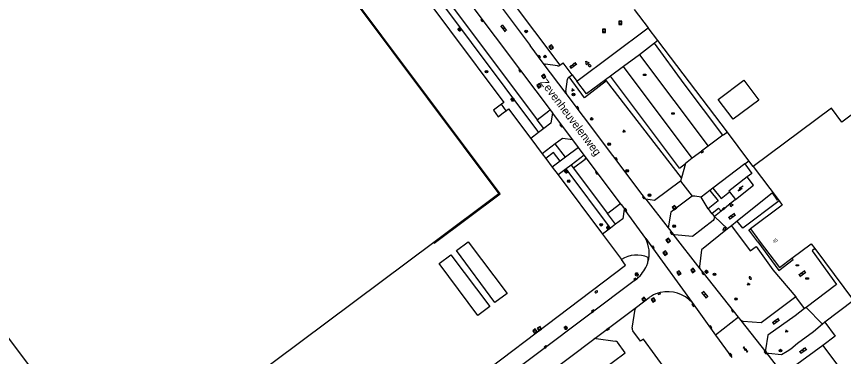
# Model space of a CAD drawing. Extents: x 130998 to 133001, y 398999 to 403002.
# Drawn here: x 131205.8 to 131464.1, y 399814.9 to 399921.1 of the extents above; entities that cross this region are included whole.
import ezdxf

# ---------------------------------------------------------------- set-up
doc = ezdxf.new("R2010")
doc.units = 0
for name, color, linetype in [('gg-afsc-haag', 7, 'Continuous'), ('gg-afsc-hekwerk', 7, 'Continuous'), ('gg-anno-huisnummerreeks BGT', 7, 'Continuous'), ('gg-anno-openbare ruimte label', 7, 'Continuous'), ('gg-bbg-bijgebouw', 7, 'Continuous'), ('gg-bbg-hoofdgebouw', 7, 'Continuous'), ('gg-bbg-lage trafo', 7, 'Continuous'), ('gg-bbg-luifel en loopbrug', 7, 'Continuous'), ('gg-bbg-onder overbouw', 7, 'Continuous'), ('gg-bbg-pand overbouw', 7, 'Continuous'), ('gg-knt-verharding', 7, 'Continuous'), ('gg-knt-verharding nz', 7, 'Continuous'), ('gt-grn-groengrens', 7, 'Continuous'), ('gt-grn-vlakafsluiter', 7, 'Continuous'), ('gt-grn-weggrens', 7, 'Continuous'), ('gt-symb-boom', 7, 'Continuous'), ('gt-symb-brandkraan', 7, 'Continuous'), ('gt-symb-gesloten verharding', 7, 'Continuous'), ('gt-symb-groenvak', 7, 'Continuous'), ('gt-symb-klinker verharding', 7, 'Continuous'), ('gt-symb-kolk', 7, 'Continuous'), ('gt-symb-kolk center center', 7, 'Continuous'), ('gt-symb-lichtmast', 7, 'Continuous'), ('gt-symb-rioolschacht', 7, 'Continuous'), ('gt-symb-trafo symbool', 7, 'Continuous'), ('gt-symb-waterafsluiter', 7, 'Continuous')]:
    doc.layers.add(name, color=color, linetype=linetype)

# ---------------------------------------------------------------- blocks, each defined once
blk = doc.blocks.new('gt0-KL1')
at = {"layer": 'gt-symb-klinker verharding'}
for p, q in [((-1.15, 0.3), (1.15, 0.3)), ((-1, -0.3), (-1, 0.3)), ((-0.5, 0.3), (-0.5, 0.45)), ((0, -0.3), (0, 0.3)), ((0.5, 0.3), (0.5, 0.45)), ((1, -0.3), (1, 0.3)), ((-1.15, -0.3), (1.15, -0.3)), ((-0.5, -0.45), (-0.5, -0.3)), ((0.5, -0.45), (0.5, -0.3))]:
    blk.add_line(p, q, dxfattribs=at)
blk = doc.blocks.new('gt0-KOLKCC')
at = {"layer": 'gt-symb-kolk center center'}
blk.add_lwpolyline([(-0.38, 0.2), (0.38, 0.2), (0.38, -0.2), (-0.38, -0.2)], close=True, dxfattribs=at)
blk = doc.blocks.new('gt0-KOLK')
at = {"layer": 'gt-symb-kolk'}
blk.add_lwpolyline([(0, 0), (0.37, 0), (0.37, 0.4), (-0.38, 0.4), (-0.38, 0), (0, 0)], dxfattribs=at)
blk = doc.blocks.new('gt0-BOOM')
at = {"layer": 'gt-symb-boom'}
for radius in [0.4, 0.2]:
    blk.add_circle((0, 0), radius, dxfattribs=at)
blk = doc.blocks.new('gt0-GRVAK')
at = {"layer": 'gt-symb-groenvak'}
for p, q in [((-0.11, 0.19), (-0.23, 0.24)), ((-0.18, 0.15), (0.09, 0.15)), ((-0.09, 0.21), (-0.16, 0.32)), ((-0.05, 0.21), (-0.05, 0.39)), ((0, 0.21), (0.06, 0.32)), ((0.01, 0.19), (0.13, 0.24)), ((0.26, -0.05), (0.2, 0.06)), ((0.3, -0.05), (0.3, 0.13)), ((0.35, -0.05), (0.41, 0.06)), ((-0.24, -0.23), (-0.36, -0.18)), ((-0.32, -0.26), (-0.05, -0.26)), ((-0.23, -0.21), (-0.29, -0.09)), ((-0.18, -0.2), (-0.18, -0.02)), ((-0.14, -0.21), (-0.07, -0.09)), ((-0.12, -0.23), (0, -0.18)), ((0.24, -0.07), (0.12, -0.02)), ((0.17, -0.11), (0.44, -0.11)), ((0.37, -0.07), (0.49, -0.02))]:
    blk.add_line(p, q, dxfattribs=at)
blk = doc.blocks.new('gt0-WAFSL')
at = {"layer": 'gt-symb-waterafsluiter'}
for p, q in [((-0.5, -0.33), (0, 0.67)), ((0, 0.67), (0.5, -0.33)), ((0.5, -0.33), (-0.5, -0.33))]:
    blk.add_line(p, q, dxfattribs=at)
blk = doc.blocks.new('gt0-HSP')
at = {"layer": 'gt-symb-trafo symbool'}
for points in [[(0.77, 0.75), (-0.53, 0), (0.47, 0), (-0.83, -0.75)], [(-0.22, -0.24), (-0.83, -0.75), (-0.08, -0.48)]]:
    blk.add_lwpolyline(points, dxfattribs=at)
blk = doc.blocks.new('gt0-BR')
at = {"layer": 'gt-symb-brandkraan'}
for centre, radius, start, end in [((-0.24, 0), 0.206, 107.5669, 252.4331), ((0.6, -2.66), 3, 106.892, 107.5669), ((0, -0.69), 0.938, 73.108, 106.892), ((-0.6, -2.66), 3, 72.4331, 73.108), ((0.24, 0), 0.206, 287.567, 72.4331), ((0.6, 2.66), 3, 252.4331, 253.108), ((0, 0.69), 0.938, 253.108, 286.8921), ((-0.6, 2.66), 3, 286.8921, 287.567)]:
    blk.add_arc(centre, radius, start, end, dxfattribs=at)
blk = doc.blocks.new('gt0-LMAST')
at = {"layer": 'gt-symb-lichtmast'}
for p, q in [((-0.18, 0.17), (-0.45, 0.44)), ((-0.01, 0.25), (-0.01, 0.62)), ((0.17, 0.17), (0.44, 0.44)), ((-0.26, 0), (-0.63, 0)), ((-0.18, -0.18), (-0.45, -0.45)), ((-0.01, -0.25), (-0.01, -0.63)), ((0.44, -0.45), (0.17, -0.18)), ((0.24, 0), (0.62, 0))]:
    blk.add_line(p, q, dxfattribs=at)
blk.add_circle((-0.01, 0), 0.25, dxfattribs=at)
blk = doc.blocks.new('gt0-RS')
at = {"layer": 'gt-symb-rioolschacht'}
blk.add_lwpolyline([(-0.5, -0.5), (0.5, -0.5), (0.5, 0.5), (-0.5, 0.5)], close=True, dxfattribs=at)
blk.add_circle((0, 0), 0.375, dxfattribs=at)
blk = doc.blocks.new('gt0-GESVH1')
at = {"layer": 'gt-symb-gesloten verharding'}
for p, q in [((-0.99, -0.26), (0.01, 0.24)), ((0.01, -0.26), (-0.99, 0.24)), ((0.01, 0.24), (1.01, -0.26)), ((1.01, 0.24), (0.01, -0.26))]:
    blk.add_line(p, q, dxfattribs=at)

msp = doc.modelspace()

# ---------------------------------------------------------------- linework, layer by layer
at = {"layer": 'gg-afsc-haag'}
msp.add_line((131350.4, 399939.47), (131375.52, 399905.9), dxfattribs=at)
at = {"layer": 'gg-afsc-hekwerk'}
for p, q in [((131398.73, 399923.33), (131403.08, 399917.6)), ((131406.13, 399913.58), (131403.08, 399917.6)), ((131427.86, 399884.95), (131406.13, 399913.58)), ((131366.44, 399883.03), (131370.03, 399878.24)), ((131434.61, 399876.04), (131427.86, 399884.95)), ((131370.03, 399878.24), (131371.11, 399876.78)), ((131371.11, 399876.78), (131373.14, 399874.08)), ((131435.95, 399874.28), (131434.61, 399876.04)), ((131373.14, 399874.08), (131374.96, 399871.64)), ((131374.96, 399871.64), (131388.81, 399853.12)), ((131388.81, 399853.12), (131394.77, 399845.15)), ((131467.32, 399832.34), (131458.31, 399825.62)), ((131457.71, 399818.34), (131465.17, 399808.41))]:
    msp.add_line(p, q, dxfattribs=at)
for points in [[(131255.4, 400029.91), (131256.2, 400030.54), (131358.05, 399894.24), (131357.29, 399893.68)], [(131358.76, 399891.64), (131359.53, 399892.28), (131366.44, 399883.03)], [(131262.93, 399742.61), (131396.05, 399843.43), (131394.77, 399845.15)], [(131458.31, 399825.62), (131461.59, 399821.26), (131457.71, 399818.34)]]:
    msp.add_lwpolyline(points, dxfattribs=at)
at = {"layer": 'gg-bbg-bijgebouw'}
for p, q in [((131423.85, 399858.68), (131423.08, 399859.67)), ((131425.91, 399860.27), (131423.85, 399858.68))]:
    msp.add_line(p, q, dxfattribs=at)
msp.add_lwpolyline([(131423.08, 399859.67), (131425.14, 399861.26), (131425.91, 399860.27)], dxfattribs=at)
at = {"layer": 'gg-bbg-hoofdgebouw'}
for p, q in [((131435.95, 399874.28), (131443.73, 399863.9)), ((131428.49, 399866.31), (131430.38, 399863.92)), ((131443.73, 399863.9), (131444.03, 399863.5)), ((131435.05, 399854.76), (131437.06, 399852.07)), ((131437.06, 399852.07), (131437.84, 399851.04)), ((131455.18, 399848.61), (131467.32, 399832.34))]:
    msp.add_line(p, q, dxfattribs=at)
for points in [[(131336.13, 399850.49), (131236.57, 399776.11), (131107.17, 399949.27), (131206.75, 400023.65)], [(131528.02, 399861.02), (131492, 399909.25), (131463.68, 399888.1), (131460.37, 399892.52), (131435.95, 399874.28)], [(131434.05, 399870.98), (131434.01, 399871.03), (131428.32, 399866.52), (131428.49, 399866.31)], [(131430.38, 399863.92), (131436.07, 399868.43), (131434.05, 399870.98)], [(131444.03, 399863.5), (131445, 399862.21), (131435.05, 399854.76)], [(131437.84, 399851.04), (131444.12, 399842.65), (131448.06, 399845.59)], [(131448.06, 399845.59), (131454.08, 399850.09), (131455.18, 399848.61)]]:
    msp.add_lwpolyline(points, dxfattribs=at)
at = {"layer": 'gg-bbg-lage trafo'}
msp.add_line((131358.76, 399891.64), (131357.29, 399893.68), dxfattribs=at)
msp.add_lwpolyline([(131357.29, 399893.68), (131356.51, 399893.05), (131354.74, 399891.85), (131356.25, 399889.81), (131357.92, 399891.1), (131358.76, 399891.64)], dxfattribs=at)
at = {"layer": 'gg-bbg-luifel en loopbrug'}
for points in [[(131425.03, 399895.19), (131433.05, 399901.2), (131437.7, 399895), (131429.67, 399888.99), (131425.03, 399895.19)], [(131343.25, 399848), (131346.9, 399850.7), (131359.02, 399834.54), (131355.24, 399831.71), (131343.25, 399848)], [(131337.84, 399843.94), (131341.51, 399846.66), (131353.61, 399830.49), (131349.86, 399827.68), (131337.84, 399843.94)]]:
    msp.add_lwpolyline(points, dxfattribs=at)
at = {"layer": 'gg-bbg-onder overbouw'}
msp.add_lwpolyline([(131206.75, 400023.65), (131208.07, 400024.63), (131208.07, 400024.62), (131227.08, 400038.81), (131233.54, 400030.08), (131233.55, 400030.09), (131356.47, 399865.68), (131336.13, 399850.49)], dxfattribs=at)
at = {"layer": 'gg-bbg-pand overbouw'}
msp.add_lwpolyline([(131336.13, 399850.49), (131336.29, 399850.27), (131356.85, 399865.66), (131227.03, 400039.25), (131206.6, 400023.86), (131206.75, 400023.65)], dxfattribs=at)
at = {"layer": 'gg-knt-verharding'}
for p, q in [((131248.82, 400045.24), (131368.9, 399884.87)), ((131253.49, 400042.39), (131368.48, 399888.87)), ((131350.35, 399933.3), (131366.25, 399912.07)), ((131406.13, 399913.58), (131405.08, 399912.81)), ((131370.34, 399906.58), (131366.25, 399912.07)), ((131374.79, 399905.7), (131371, 399906.26)), ((131375.52, 399905.9), (131376.59, 399906.68)), ((131377.37, 399897.66), (131377.9, 399901.5)), ((131378.31, 399902.15), (131378.41, 399902.23)), ((131378.41, 399902.23), (131379.34, 399902.91)), ((131379.34, 399902.91), (131380.82, 399900.92)), ((131391.33, 399902.5), (131389.79, 399901.36)), ((131412.88, 399873.73), (131391.33, 399902.5)), ((131382.9, 399889.86), (131377.53, 399897.04)), ((131368.48, 399888.87), (131372.12, 399891.61)), ((131372.81, 399891.51), (131373.21, 399891)), ((131370.51, 399886.09), (131368.9, 399884.87)), ((131368.9, 399884.87), (131366.44, 399883.03)), ((131426.5, 399884.05), (131421.84, 399880.57)), ((131374.09, 399881.28), (131370.03, 399878.24)), ((131377.25, 399877.13), (131374.09, 399881.28)), ((131381.31, 399880.2), (131377.25, 399877.13)), ((131381.31, 399880.2), (131379.57, 399882.54)), ((131383.16, 399877.8), (131381.31, 399880.2)), ((131383.16, 399877.8), (131379.04, 399874.71)), ((131383.55, 399877.26), (131383.16, 399877.8)), ((131375.6, 399875.92), (131373.14, 399874.08)), ((131379.79, 399873.82), (131383.45, 399876.57)), ((131412.88, 399873.73), (131414.8, 399875.23)), ((131414.8, 399875.23), (131413.49, 399870.72)), ((131416.92, 399876.81), (131414.8, 399875.23)), ((131433.31, 399875.1), (131423.28, 399867.43)), ((131433.31, 399875.1), (131434.61, 399876.04)), ((131377.46, 399873.5), (131374.96, 399871.64)), ((131391.35, 399855.02), (131377.46, 399873.5)), ((131390.48, 399859.61), (131379.79, 399873.82)), ((131413.49, 399870.72), (131413.18, 399869.63)), ((131423.28, 399867.43), (131422.37, 399866.73)), ((131417.67, 399864.94), (131416.87, 399865.03)), ((131419.72, 399864.71), (131417.67, 399864.94)), ((131422.37, 399866.73), (131419.72, 399864.71)), ((131441.97, 399865.99), (131430.97, 399857.17)), ((131394.12, 399862.35), (131390.48, 399859.61)), ((131430.97, 399857.17), (131429.12, 399855.7)), ((131391.35, 399855.02), (131388.81, 399853.12)), ((131392.95, 399856.22), (131391.35, 399855.02)), ((131409.37, 399855.08), (131410.89, 399853.14)), ((131429.12, 399855.7), (131427.94, 399854.75)), ((131399.45, 399830.31), (131403.46, 399833.33)), ((131416.83, 399831.73), (131424.19, 399821.55)), ((131398.12, 399823.7), (131399.03, 399829.65)), ((131452.45, 399830.23), (131452.01, 399829.9)), ((131431.39, 399827.15), (131424.19, 399821.55)), ((131432.2, 399826.11), (131431.39, 399827.15)), ((131439.98, 399816.22), (131432.2, 399826.11)), ((131458.31, 399825.62), (131457.62, 399825.02)), ((131424.19, 399821.55), (131429.22, 399814.59)), ((131368.76, 399807.23), (131386.13, 399820.3)), ((131386.89, 399820.49), (131392.84, 399819.73)), ((131448.22, 399805.64), (131439.98, 399816.22))]:
    msp.add_line(p, q, dxfattribs=at)
for points in [[(131426.5, 399884.05), (131414.42, 399900.06), (131405.08, 399912.81)], [(131389.79, 399901.36), (131383.82, 399896.91), (131380.82, 399900.92)], [(131373.21, 399891), (131372.75, 399887.78), (131370.51, 399886.09)], [(131370.51, 399886.09), (131368.45, 399888.84), (131368.48, 399888.87)], [(131402.34, 399864.07), (131401.21, 399865.49), (131382.9, 399889.86)], [(131379.57, 399882.54), (131376.35, 399882.99), (131374.09, 399881.28)], [(131427.86, 399884.95), (131426.7, 399884.04), (131426.6, 399884.13), (131426.5, 399884.05)], [(131421.84, 399880.57), (131419.83, 399879.07), (131419.85, 399879.03), (131416.92, 399876.81)], [(131375.6, 399875.92), (131373.58, 399878.63), (131371.11, 399876.78)], [(131433.31, 399875.1), (131435.54, 399872.11), (131434.05, 399870.98)], [(131379.04, 399874.71), (131379.75, 399873.78), (131379.79, 399873.82)], [(131413.18, 399869.63), (131405.14, 399863.61), (131402.34, 399864.07)], [(131423.28, 399867.43), (131425.89, 399864.25), (131428.49, 399866.31)], [(131416.87, 399865.03), (131410.17, 399859.99), (131409.37, 399855.08)], [(131422.37, 399866.73), (131424.97, 399863.56), (131421.83, 399861.02)], [(131443.73, 399863.9), (131443.52, 399863.71), (131441.97, 399865.99)], [(131394.8, 399862.27), (131395.67, 399861.11), (131395.65, 399860.93)], [(131444.03, 399863.5), (131432.7, 399855.01), (131430.97, 399857.17)], [(131392.95, 399856.22), (131390.44, 399859.59), (131390.48, 399859.61)], [(131395.65, 399860.93), (131395.22, 399857.92), (131392.95, 399856.22)], [(131421.83, 399861.02), (131422.95, 399859.57), (131423.08, 399859.67)], [(131423.42, 399857.34), (131416.93, 399852.43), (131411.33, 399852.9), (131411.08, 399852.97), (131410.89, 399853.14)], [(131423.85, 399858.68), (131423.68, 399857.73), (131423.42, 399857.34)], [(131427.94, 399854.75), (131419.77, 399848.2), (131419.16, 399842.99), (131419.2, 399842.65), (131419.34, 399842.33)], [(131429.12, 399855.7), (131435.03, 399847.95), (131436.84, 399849.27)], [(131437.41, 399850.73), (131434.62, 399854.44), (131435.05, 399854.76)], [(131402.36, 399851.76), (131404.44, 399848.88), (131416.83, 399831.73)], [(131436.84, 399849.27), (131442.11, 399842), (131449.27, 399833.56)], [(131437.41, 399850.73), (131444, 399841.76), (131448.46, 399845.2), (131448.06, 399845.59)], [(131455.18, 399848.61), (131454.36, 399847.91), (131462.01, 399837.39), (131452.45, 399830.23)], [(131431.39, 399827.15), (131420.4, 399841.05), (131419.34, 399842.33)], [(131399.69, 399839.18), (131399.29, 399838.88), (131399.14, 399838.82), (131338.35, 399793.11), (131321.95, 399780.8), (131304.77, 399767.85), (131265.93, 399738.67)], [(131406.23, 399834.67), (131406.54, 399834.76), (131406.97, 399834.85)], [(131449.27, 399833.56), (131438.47, 399825.46), (131432.77, 399825.82), (131432.47, 399825.93), (131432.2, 399826.11)], [(131452.01, 399829.9), (131449.02, 399827.61), (131440.55, 399821.53)], [(131457.62, 399825.02), (131454.8, 399822.58), (131449.8, 399818.93), (131447.67, 399817.18), (131446.58, 399816.48)], [(131441.74, 399765.29), (131401.62, 399820.31), (131400.77, 399819.72), (131398.35, 399822.96)], [(131440.55, 399821.53), (131439.79, 399816.94), (131439.8, 399816.56), (131439.98, 399816.22)], [(131388.66, 399810.58), (131395.95, 399816.07), (131393.51, 399819.36)], [(131457.71, 399818.34), (131448.44, 399811.54), (131447.94, 399806.46), (131448.06, 399805.91), (131448.22, 399805.64)], [(131446.58, 399816.48), (131444.74, 399815.36), (131440.69, 399815.83), (131440.3, 399815.95), (131439.98, 399816.22)]]:
    msp.add_lwpolyline(points, dxfattribs=at)
for centre, radius, start, end in [((131371, 399907.11), 0.852, 218.3923, 269.9298), ((131374.92, 399906.65), 0.959, 261.7853, 308.0579), ((131378.67, 399901.47), 0.77, 118.291, 178.4064), ((131378.33, 399897.57), 0.959, 175.1869, 213.7198), ((131372.41, 399891.2), 0.504, 38.2604, 125.9433), ((131383.14, 399876.97), 0.502, 308.1737, 35.776), ((131394.42, 399861.96), 0.489, 38.8302, 127.7502), ((131399.55, 399837.86), 8.72, 65.9183, 123.2656), ((131397.69, 399845.36), 5.44, 337.7806, 350.3682), ((131397.64, 399845.36), 5.49, 350.4703, 4.7403), ((131390.1, 399849.41), 14.02, 313.1208, 334.1985), ((131409.51, 399824.38), 10.81, 107.6984, 124.0293), ((131409.33, 399825.17), 9.97, 41.1945, 103.7188), ((131400.18, 399829.38), 1.18, 128.0419, 167.0046), ((131399.01, 399823.57), 0.897, 171.6986, 223.1236), ((131386.75, 399819.46), 1.04, 82.3712, 126.4135), ((131392.81, 399818.89), 0.841, 34.0103, 88.0262)]:
    msp.add_arc(centre, radius, start, end, dxfattribs=at)
at = {"layer": 'gg-knt-verharding nz'}
for p, q in [((131380.82, 399900.92), (131403.08, 399917.6)), ((131405.08, 399912.81), (131400.37, 399909.16)), ((131400.37, 399909.16), (131395.43, 399905.45)), ((131400.37, 399909.16), (131421.84, 399880.57)), ((131377.53, 399897.04), (131370.34, 399906.58)), ((131395.43, 399905.45), (131391.33, 399902.5)), ((131416.92, 399876.81), (131395.43, 399905.45)), ((131379.57, 399882.54), (131373.21, 399891)), ((131377.25, 399877.13), (131375.6, 399875.92)), ((131379.04, 399874.71), (131377.46, 399873.5)), ((131402.34, 399864.07), (131409.37, 399855.08)), ((131430.38, 399863.92), (131425.91, 399860.27)), ((131402.27, 399851.72), (131402.36, 399851.76)), ((131419.34, 399842.33), (131410.89, 399853.14)), ((131386.13, 399820.3), (131399.45, 399830.31))]:
    msp.add_line(p, q, dxfattribs=at)
for points in [[(131335.62, 399941.07), (131339.49, 399935.93), (131363.21, 399904.29), (131372.81, 399891.51)], [(131394.8, 399862.27), (131387.18, 399872.37), (131383.55, 399877.26)], [(131402.36, 399851.76), (131395.91, 399860.6), (131395.65, 399860.93)]]:
    msp.add_lwpolyline(points, dxfattribs=at)
msp.add_arc((131394.44, 399847.2), 9.03, 342.3318, 30.0228, dxfattribs=at)
at = {"layer": 'gt-grn-groengrens'}
for p, q in [((131390.08, 399900.98), (131389.79, 399901.36)), ((131413.49, 399870.72), (131390.08, 399900.98)), ((131421.83, 399861.02), (131419.72, 399864.71)), ((131452.45, 399830.23), (131457.62, 399825.02))]:
    msp.add_line(p, q, dxfattribs=at)
msp.add_lwpolyline([(131390.08, 399900.98), (131383.26, 399895.71), (131378.41, 399902.23)], dxfattribs=at)
at = {"layer": 'gt-grn-vlakafsluiter'}
msp.add_line((131379.34, 399902.91), (131376.59, 399906.68), dxfattribs=at)
at = {"layer": 'gt-grn-weggrens'}
for p, q in [((131413.18, 399869.63), (131416.87, 399865.03)), ((131423.85, 399858.68), (131427.94, 399854.75)), ((131452.01, 399829.9), (131449.27, 399833.56))]:
    msp.add_line(p, q, dxfattribs=at)

# ---------------------------------------------------------------- block references
at = {"layer": 'gt-symb-boom'}
for p in [(131365.02, 399916.46), (131370.9, 399908.59), (131352.61, 399903.87), (131379.79, 399896.75), (131385.46, 399889.11), (131390.92, 399881.24), (131396.58, 399872.91), (131378.28, 399869.67), (131403.53, 399865.31), (131388.45, 399856.06), (131411.25, 399855.61), (131423.86, 399840.57), (131430.58, 399832.85), (131444.45, 399816.73)]:
    msp.add_blockref('gt0-BOOM', p, dxfattribs=at)
at = {"layer": 'gt-symb-brandkraan'}
for p, rotation in [((131384.84, 399905.75), -25.719512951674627), ((131435, 399839.41), 134.43273358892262), ((131386.91, 399835.11), 31.877816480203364)]:
    msp.add_blockref('gt0-BR', p, dxfattribs=dict(at, rotation=rotation))
at = {"layer": 'gt-symb-gesloten verharding', "rotation": -51.82346239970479}
msp.add_blockref('gt0-GESVH1', (131433.52, 399817.07), dxfattribs=at)
at = {"layer": 'gt-symb-groenvak'}
for p in [(131379.56, 399898.18), (131395.57, 399885.31), (131434.46, 399837.52), (131446.34, 399822.83)]:
    msp.add_blockref('gt0-GRVAK', p, dxfattribs=at)
at = {"layer": 'gt-symb-klinker verharding'}
for p, rotation in [((131357.93, 399917.43), -51.82346239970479), ((131379.69, 399905.86), 37.11068297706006), ((131429.33, 399858.73), 35.72413480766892), ((131451.32, 399840.83), 35.690714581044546), ((131420.77, 399834.21), -51.82346239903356), ((131443.04, 399825.94), 35.67760208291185), ((131451.54, 399816.8), 35.67760208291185)]:
    msp.add_blockref('gt0-KL1', p, dxfattribs=dict(at, rotation=rotation))
at = {"layer": 'gt-symb-kolk'}
for p, rotation in [((131351.39, 399920.05), 126.85214302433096), ((131368.97, 399908.43), -53.54278990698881), ((131363.21, 399904.29), 126.8586002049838), ((131380.94, 399892.46), -53.13010235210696), ((131376.08, 399887.19), 126.89894820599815), ((131419.83, 399879.07), -143.21030035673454), ((131392.95, 399876.48), -53.5427899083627), ((131387.18, 399872.37), 126.62132749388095), ((131401.85, 399864.71), 128.01566048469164), ((131395.91, 399860.6), -53.90973140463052), ((131410.55, 399853.56), 127.93526324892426), ((131404.44, 399848.88), -53.909432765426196), ((131420.4, 399841.05), 128.30199382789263), ((131399.14, 399838.82), 36.95012773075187), ((131406.54, 399834.76), -164.15691788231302), ((131417.33, 399831.07), 126.78969964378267), ((131385.95, 399828.89), 36.950127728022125), ((131429.68, 399829.3), 128.38245733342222), ((131422.46, 399823.93), -54.115886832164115), ((131371.14, 399817.75), 36.91570677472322), ((131428.68, 399815.34), -54.069481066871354), ((131439.93, 399816.28), 128.22155685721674)]:
    msp.add_blockref('gt0-KOLK', p, dxfattribs=dict(at, rotation=rotation))
at = {"layer": 'gt-symb-kolk center center'}
for p in [(131402.04, 399902.86), (131410.9, 399890.81), (131449.75, 399843.37), (131452.8, 399839.26)]:
    msp.add_blockref('gt0-KOLKCC', p, dxfattribs=at)
for p, rotation in [((131426.73, 399861.09), -141.9039146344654), ((131390.5, 399823.41), 36.09056723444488)]:
    msp.add_blockref('gt0-KOLKCC', p, dxfattribs=dict(at, rotation=rotation))
at = {"layer": 'gt-symb-lichtmast'}
for p in [(131344.19, 399917.07), (131360.76, 399895.14), (131377.55, 399872.67), (131390.66, 399855.1), (131421.37, 399841.37), (131399.55, 399840.56), (131377.38, 399823.81)]:
    msp.add_blockref('gt0-LMAST', p, dxfattribs=at)
at = {"layer": 'gt-symb-rioolschacht'}
for p in [(131394.41, 399919.14), (131389.33, 399916.65)]:
    msp.add_blockref('gt0-RS', p, dxfattribs=at)
for p, rotation in [((131372.81, 399911.55), -53.21030035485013), ((131370.48, 399902.4), 126.29695894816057), ((131369.01, 399899.46), 126.37706752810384), ((131411.33, 399861.41), 131.30991847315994), ((131409.38, 399851.15), 126.37706752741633), ((131408.43, 399847.18), -55.38819363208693), ((131412.74, 399840.98), -54.11588683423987), ((131417.12, 399841.74), -53.989474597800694), ((131401.81, 399832.73), 36.66359246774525), ((131404.74, 399832.55), 29.666715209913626), ((131367.74, 399822.82), 36.58342113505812), ((131369.13, 399823.59), 28.820835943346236)]:
    msp.add_blockref('gt0-RS', p, dxfattribs=dict(at, rotation=rotation))
at = {"layer": 'gt-symb-trafo symbool'}
msp.add_blockref('gt0-HSP', (131432.04, 399867.4), dxfattribs=at)
at = {"layer": 'gt-symb-waterafsluiter'}
for p, rotation in [((131384.06, 399906.61), 37.156374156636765), ((131429.09, 399862.25), 38.382457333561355)]:
    msp.add_blockref('gt0-WAFSL', p, dxfattribs=dict(at, rotation=rotation))
msp.add_blockref('gt0-WAFSL', (131426.92, 399854.71), dxfattribs=at)

# ---------------------------------------------------------------- texts
at = {"layer": 'gg-anno-huisnummerreeks BGT'}
msp.add_text('45', height=1, rotation=36.8, dxfattribs=at).set_placement((131442.48, 399850.22))
at = {"layer": 'gg-anno-openbare ruimte label'}
msp.add_text('Zevenheuvelenweg', height=2.5, rotation=307, dxfattribs=at).set_placement((131369.22, 399900.49))

doc.saveas('drawing.dxf')
